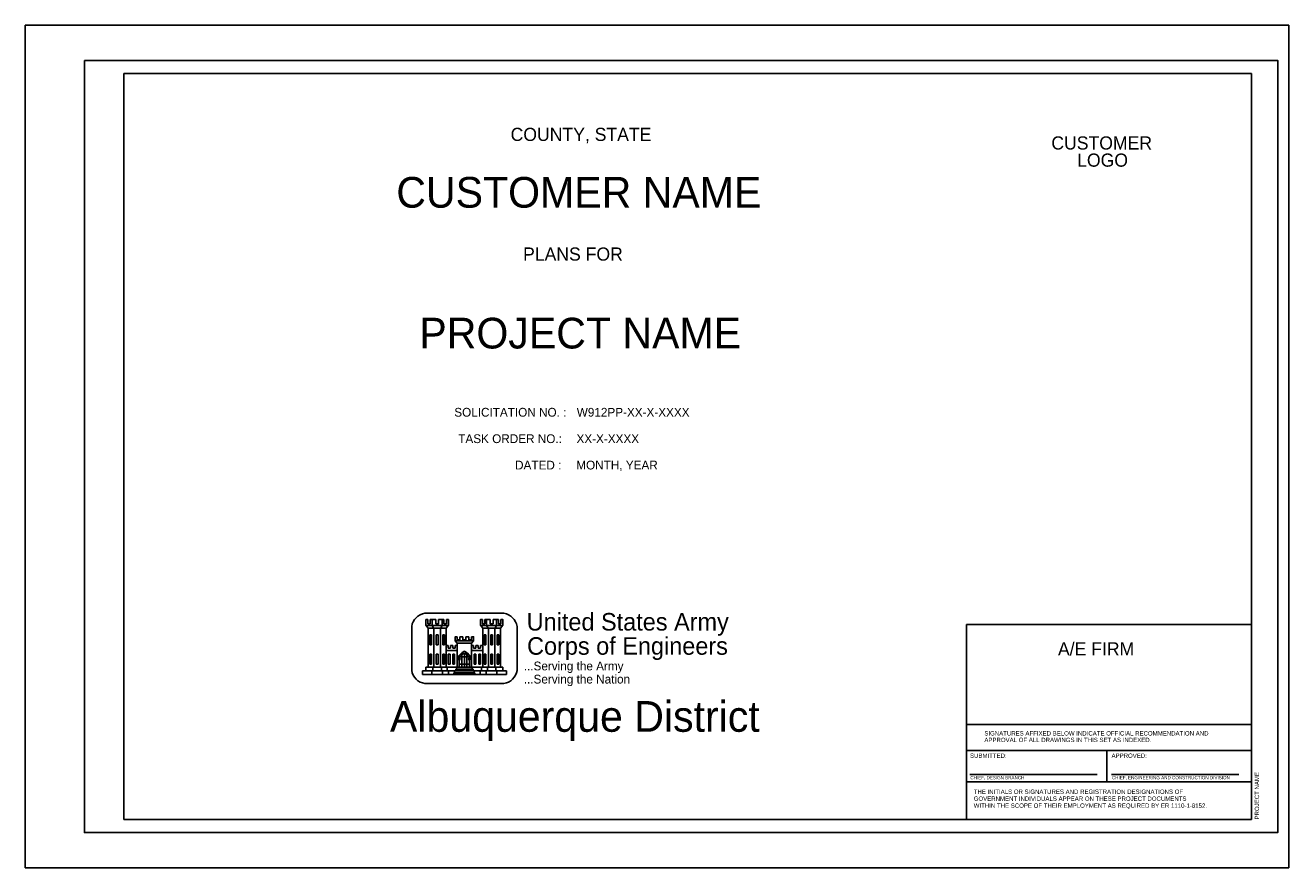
# Model space of a CAD drawing. Extents: x 0 to 288, y 0 to 192.
import ezdxf

# ---------------------------------------------------------------- set-up
doc = ezdxf.new("R2010")
doc.units = 0
for name, color, linetype in [('G-ANNO-SYMB', 7, 'Continuous'), ('G-ANNO-TEXT', 7, 'Continuous'), ('G-ANNO-TTBL', 7, 'Continuous')]:
    doc.layers.add(name, color=color, linetype=linetype)

msp = doc.modelspace()

# ---------------------------------------------------------------- linework, layer by layer
at = {"layer": 'G-ANNO-SYMB'}
for p, q in [((109.09, 57.98), (91.09, 57.98)), ((88.09, 54.98), (88.09, 44.98)), ((112.09, 44.98), (112.09, 54.98)), ((98.94, 47.55), (98.94, 47.55)), ((90.51, 44.87), (91.32, 44.87)), ((91.32, 45.68), (91.86, 45.68)), ((108.86, 45.68), (108.32, 45.68)), ((109.67, 44.87), (108.86, 44.87)), ((91.09, 41.98), (109.09, 41.98))]:
    msp.add_line(p, q, dxfattribs=at)
for points in [[(91.79, 56.55), (91.32, 56.55), (91.32, 55.25), (91.86, 54.58), (91.86, 45.68)], [(96.41, 55.19), (91.37, 55.19)], [(92.33, 56.55), (92.33, 55.6), (91.79, 55.6), (91.79, 56.55)], [(92.33, 56.55), (93.55, 56.55)], [(92.74, 56.55), (92.74, 55.22), (93.14, 54.54), (93.14, 45.68)], [(94.22, 56.55), (94.22, 55.6), (93.55, 55.6), (93.55, 56.55)], [(94.22, 56.55), (95.43, 56.55)], [(95.03, 56.55), (95.03, 55.22), (94.63, 54.54), (94.63, 45.68)], [(95.98, 56.55), (95.98, 55.6), (95.43, 55.6), (95.43, 56.55)], [(95.98, 56.55), (96.45, 56.55), (96.45, 55.25), (95.91, 54.58), (95.91, 45.68)], [(104.21, 56.55), (103.74, 56.55), (103.74, 55.25), (104.27, 54.58), (104.27, 45.68)], [(103.78, 55.19), (108.82, 55.19)], [(104.21, 56.55), (104.21, 55.6), (104.75, 55.6), (104.75, 56.55)], [(105.96, 56.55), (104.75, 56.55)], [(105.15, 56.55), (105.15, 55.22), (105.56, 54.54), (105.56, 45.68)], [(105.96, 56.55), (105.96, 55.6), (106.64, 55.6), (106.64, 56.55)], [(107.85, 56.55), (106.64, 56.55)], [(107.45, 56.55), (107.45, 55.22), (107.04, 54.54), (107.04, 45.68)], [(107.85, 56.55), (107.85, 55.6), (108.39, 55.6), (108.39, 56.55)], [(108.39, 56.55), (108.86, 56.55), (108.86, 55.25), (108.32, 54.58), (108.32, 45.68)], [(95.92, 54.59), (91.85, 54.59)], [(92.6, 53.1), (92.2, 53.1)], [(92.2, 53.1), (92.2, 50.81)], [(92.6, 53.1), (92.6, 50.81)], [(93.69, 53.1), (94.09, 53.1)], [(93.69, 53.1), (93.69, 50.81)], [(94.09, 53.1), (94.09, 50.81)], [(95.17, 53.1), (95.17, 50.81)], [(95.17, 53.1), (95.57, 53.1)], [(95.57, 53.1), (95.57, 50.81)], [(98.47, 45.68), (98.47, 51.15), (98, 51.69), (98, 52.63), (98.47, 52.63)], [(98.47, 52.63), (98.47, 51.96), (99.08, 51.96), (99.08, 52.63)], [(99.08, 52.63), (99.76, 52.63)], [(99.76, 52.63), (99.76, 51.96), (100.16, 51.96)], [(100.43, 52.63), (100.43, 51.96), (100.16, 51.96)], [(101.1, 52.63), (100.43, 52.63)], [(101.71, 52.63), (101.71, 51.96), (101.1, 51.96), (101.1, 52.63)], [(101.71, 45.68), (101.71, 51.15), (102.19, 51.69), (102.19, 52.63), (101.71, 52.63)], [(104.27, 54.59), (108.33, 54.59)], [(105.01, 53.1), (104.61, 53.1)], [(104.61, 53.1), (104.61, 50.81)], [(105.01, 53.1), (105.01, 50.81)], [(106.09, 53.1), (106.09, 50.81)], [(106.49, 53.1), (106.09, 53.1)], [(106.49, 53.1), (106.49, 50.81)], [(107.58, 53.1), (107.58, 50.81)], [(107.58, 53.1), (107.98, 53.1)], [(107.98, 53.1), (107.98, 50.81)], [(92.6, 50.81), (92.2, 50.81)], [(93.69, 50.81), (94.09, 50.81)], [(95.17, 50.81), (95.57, 50.81)], [(95.91, 50.61), (96.38, 50.61)], [(95.91, 49.53), (98.47, 49.53)], [(96.38, 50.07), (96.38, 50.61)], [(96.38, 50.07), (96.92, 50.07)], [(96.92, 50.61), (97.46, 50.61)], [(96.92, 50.07), (96.92, 50.61)], [(97.46, 50.07), (97.46, 50.61)], [(97.46, 50.07), (98, 50.07)], [(98, 50.61), (98.47, 50.61)], [(98, 50.07), (98, 50.61)], [(102.19, 51.69), (98.01, 51.69)], [(98.47, 51.15), (101.67, 51.15)], [(102.19, 50.61), (101.71, 50.61)], [(104.27, 49.53), (101.71, 49.53)], [(102.19, 50.07), (102.19, 50.61)], [(102.73, 50.07), (102.19, 50.07)], [(102.73, 50.07), (102.73, 50.61)], [(103.26, 50.61), (102.73, 50.61)], [(103.26, 50.07), (103.26, 50.61)], [(103.8, 50.07), (103.26, 50.07)], [(103.8, 50.07), (103.8, 50.61)], [(104.27, 50.61), (103.8, 50.61)], [(105.01, 50.81), (104.61, 50.81)], [(106.49, 50.81), (106.09, 50.81)], [(107.58, 50.81), (107.98, 50.81)], [(92.6, 48.65), (92.2, 48.65)], [(92.2, 48.65), (92.2, 46.36)], [(92.6, 46.36), (92.2, 46.36)], [(92.6, 48.65), (92.6, 46.36)], [(93.69, 48.65), (94.09, 48.65)], [(93.69, 48.65), (93.69, 46.36)], [(93.69, 46.36), (94.09, 46.36)], [(94.09, 48.65), (94.09, 46.36)], [(95.17, 48.65), (95.17, 46.36)], [(95.17, 48.65), (95.57, 48.65)], [(95.17, 46.36), (95.57, 46.36)], [(95.57, 48.65), (95.57, 46.36)], [(96.42, 48.65), (96.83, 48.65)], [(96.42, 48.65), (96.42, 46.36)], [(96.42, 46.36), (96.83, 46.36)], [(96.83, 48.65), (96.83, 46.36)], [(97.45, 48.65), (97.45, 46.36)], [(97.45, 48.65), (97.86, 48.65)], [(97.45, 46.36), (97.86, 46.36)], [(97.86, 48.65), (97.86, 46.36)], [(98.94, 47.55), (98.47, 47.55)], [(98.93, 47.46), (98.93, 45.7)], [(101.25, 46.39), (98.93, 46.39)], [(101.15, 48.05), (99.04, 48.05)], [(99.49, 48.51), (99.49, 45.7)], [(100.09, 48.92), (100.09, 45.7)], [(100.69, 48.51), (100.69, 45.7)], [(101.24, 47.55), (101.71, 47.55)], [(101.25, 47.46), (101.25, 45.7)], [(102.74, 48.65), (102.33, 48.65)], [(102.33, 48.65), (102.33, 46.36)], [(102.74, 46.36), (102.33, 46.36)], [(102.74, 48.65), (102.74, 46.36)], [(103.36, 48.65), (103.36, 46.36)], [(103.77, 48.65), (103.36, 48.65)], [(103.77, 46.36), (103.36, 46.36)], [(103.77, 48.65), (103.77, 46.36)], [(105.01, 48.65), (104.61, 48.65)], [(104.61, 48.65), (104.61, 46.36)], [(105.01, 46.36), (104.61, 46.36)], [(105.01, 48.65), (105.01, 46.36)], [(106.09, 48.65), (106.09, 46.36)], [(106.49, 48.65), (106.09, 48.65)], [(106.49, 46.36), (106.09, 46.36)], [(106.49, 48.65), (106.49, 46.36)], [(107.58, 48.65), (107.58, 46.36)], [(107.58, 48.65), (107.98, 48.65)], [(107.58, 46.36), (107.98, 46.36)], [(107.98, 48.65), (107.98, 46.36)], [(90.51, 44.87), (100.09, 44.87)], [(90.51, 44), (90.51, 44.87)], [(90.51, 44), (109.67, 44)], [(91.32, 44.87), (91.32, 45.68)], [(91.86, 45.68), (100.09, 45.68)], [(92.67, 44), (92.67, 44.87)], [(92.94, 44.87), (92.94, 45.68)], [(94.84, 44.87), (94.84, 45.68)], [(95.12, 44), (95.12, 44.87)], [(96.19, 44.87), (96.19, 45.68)], [(96.46, 44), (96.46, 44.87)], [(97.67, 44), (97.67, 44.45)], [(97.67, 44.45), (100.09, 44.45)], [(97.84, 44.45), (97.84, 44.87)], [(98.11, 45.26), (100.09, 45.26)], [(98.11, 44.87), (98.11, 45.26)], [(98.29, 45.26), (98.29, 45.68)], [(108.86, 45.68), (100.09, 45.68)], [(102.07, 45.26), (100.09, 45.26)], [(109.67, 44.87), (100.09, 44.87)], [(102.48, 44.45), (100.09, 44.45)], [(101.89, 45.26), (101.89, 45.68)], [(102.07, 44.87), (102.07, 45.26)], [(102.34, 44.45), (102.34, 44.87)], [(102.51, 44), (102.51, 44.45)], [(103.72, 44), (103.72, 44.87)], [(103.99, 44.87), (103.99, 45.68)], [(105.07, 44), (105.07, 44.87)], [(105.34, 44.87), (105.34, 45.68)], [(107.24, 44.87), (107.24, 45.68)], [(107.51, 44), (107.51, 44.87)], [(108.86, 44.87), (108.86, 45.68)], [(109.67, 44), (109.67, 44.87)]]:
    msp.add_lwpolyline(points, dxfattribs=at)
for centre in [(98.94, 47.55), (101.25, 47.55)]:
    msp.add_circle(centre, 0.202, dxfattribs=at)
for centre, radius, start, end in [((91.59, 54.48), 3.54, 98.1301, 171.8699), ((108.59, 54.48), 3.54, 8.1301, 81.8699), ((101.86, 45.84), 3.93, 116.7422, 149.566), ((98.32, 45.84), 3.93, 30.434, 63.2578), ((101.36, 46.29), 2.91, 115.7012, 153.9247), ((98.83, 46.31), 2.9, 25.7994, 64.0175), ((91.59, 45.48), 3.54, 188.1301, 261.8699), ((108.59, 45.48), 3.54, 278.1301, 351.8699)]:
    msp.add_arc(centre, radius, start, end, dxfattribs=at)
at = {"layer": 'G-ANNO-TEXT'}
for p, q in [((246.54, 26.71), (246.54, 19.61)), ((215.33, 21.28), (244.35, 21.28)), ((247.61, 21.28), (276.63, 21.28))]:
    msp.add_line(p, q, dxfattribs=at)
at = {"layer": 'G-ANNO-TTBL'}
for p, q in [((214.56, 32.66), (279.5, 32.66)), ((214.39, 26.71), (279.5, 26.71)), ((214.56, 19.61), (279.5, 19.61))]:
    msp.add_line(p, q, dxfattribs=at)
for points in [[(288, 192), (0, 192), (0, 0), (288, 0)], [(13.5, 184), (285.5, 184), (285.5, 8), (13.5, 8)], [(22.5, 181), (279.5, 181), (279.5, 11), (22.5, 11)], [(214.56, 55.42), (279.5, 55.42), (279.5, 11), (214.56, 11)]]:
    msp.add_lwpolyline(points, close=True, dxfattribs=at)

# ---------------------------------------------------------------- texts
at = {"layer": 'G-ANNO-SYMB'}
for s, height, p in [('United States Army', 4, (114.29, 54.05)), ('Corps of Engineers', 4, (114.38, 48.54)), ('...Serving the Army', 2, (113.63, 44.98)), ('...Serving the Nation', 2, (113.63, 41.98))]:
    msp.add_text(s, height=height, dxfattribs=at).set_placement(p)
at = {"layer": 'G-ANNO-TEXT'}
for s, height, p in [('COUNTY, STATE', 3, (110.63, 165.63)), ('CUSTOMER', 3, (233.89, 163.68)), ('LOGO', 3, (239.77, 159.77)), ('CUSTOMER NAME', 7, (84.58, 150.43)), ('PLANS FOR', 3, (113.47, 138.36)), ('PROJECT NAME', 7, (89.83, 118.34)), ('SOLICITATION NO. :', 2, (97.79, 102.8)), ('W912PP-XX-X-XXXX', 2, (125.71, 102.8)), ('TASK ORDER NO.:', 2, (98.7, 96.78)), ('XX-X-XXXX', 2, (125.65, 96.78)), ('DATED :', 2, (111.65, 90.76)), ('MONTH, YEAR', 2, (125.6, 90.77)), ('A/E FIRM', 3, (235.4, 48.38)), ('Albuquerque District', 7, (83.13, 30.98))]:
    msp.add_text(s, height=height, dxfattribs=at).set_placement(p)
msp.add_text('PROJECT NAME', height=1, rotation=90, dxfattribs=at).set_placement((281.25, 11))
at = {"layer": 'G-ANNO-TTBL'}
for s, height, p in [('APPROVAL OF ALL DRAWINGS IN THIS SET AS INDEXED.', 1, (218.62, 28.63)), ('SIGNATURES AFFIXED BELOW INDICATE OFFICIAL RECOMMENDATION AND', 1, (218.62, 30.13)), ('SUBMITTED:', 1, (215.35, 25.03)), ('APPROVED:', 1, (247.61, 25.03)), ('CHIEF, DESIGN BRANCH', 0.75, (215.43, 20.16)), ('CHIEF, ENGINEERING AND CONSTRUCTION DIVISION', 0.75, (247.7, 20.16)), ('THE INITIALS OR SIGNATURES AND REGISTRATION DESIGNATIONS OF', 1, (216.2, 16.82)), ('WITHIN THE SCOPE OF THEIR EMPLOYMENT AS REQUIRED BY ER 1110-1-8152.', 1, (216.2, 13.65)), ('GOVERNMENT INDIVIDUALS APPEAR ON THESE PROJECT DOCUMENTS', 1, (216.2, 15.24))]:
    msp.add_text(s, height=height, dxfattribs=at).set_placement(p)

doc.saveas('drawing.dxf')
